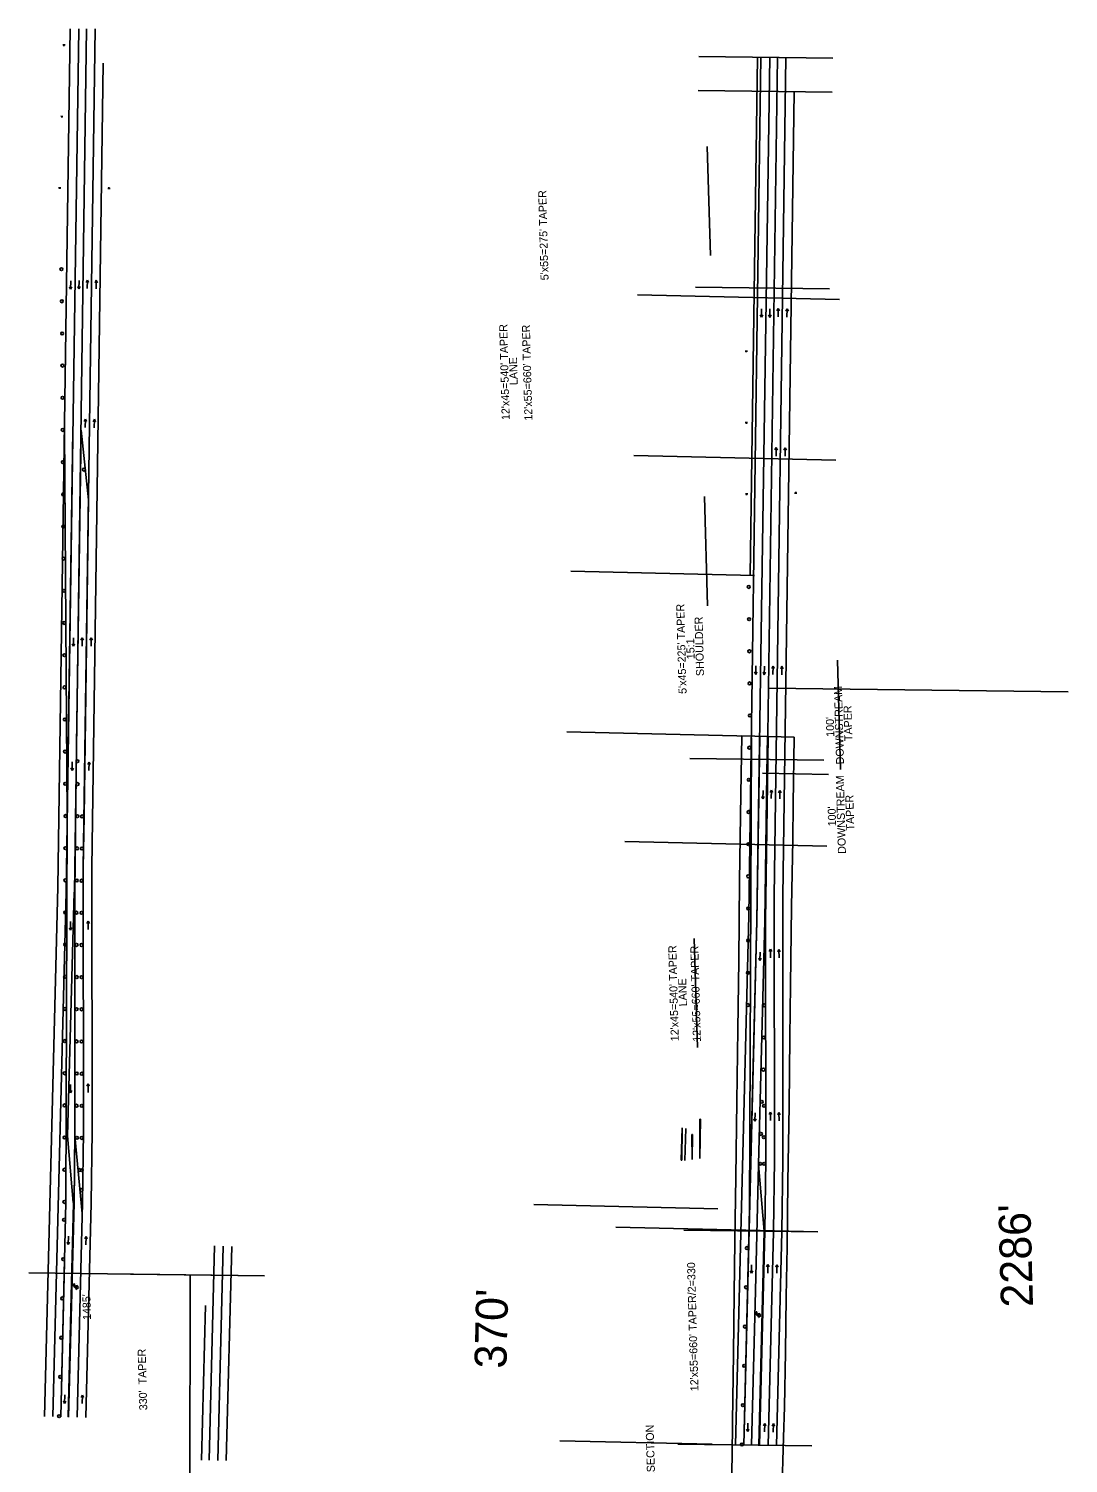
# Model space of a CAD drawing. Extents: x 1651568 to 1653044, y 601329 to 611807.
# Drawn here: x 1651589 to 1653044, y 609799 to 611807 of the extents above; entities that cross this region are included whole.
import ezdxf

# ---------------------------------------------------------------- set-up
doc = ezdxf.new("R2010")
doc.units = 0
for name, color, linetype in [('CM_Corridor_Design', 7, 'Continuous'), ('Default', 7, 'Continuous'), ('DR_X_Storm_Sewer', 7, 'Continuous'), ('DT_X_Break_Line', 7, 'Continuous'), ('GE_P_Alignment_500_Cardinal_Points', 7, 'Continuous'), ('GE_P_Alignment_500_Distances', 7, 'Continuous'), ('PF_P_Grade_Line', 7, 'Continuous'), ('PF_X_Ground_Line', 7, 'Continuous'), ('PF_X_Ground_Line_LT', 7, 'Continuous'), ('PF_X_Ground_Line_RT', 7, 'Continuous'), ('PV_P_EOP', 7, 'Continuous'), ('RW_X_Esmt_LA', 7, 'Continuous'), ('SC_Scratch3', 7, 'Continuous'), ('UT_X_Gas', 7, 'Continuous'), ('UT_X_Sanitary_Line', 7, 'Continuous')]:
    doc.layers.add(name, color=color, linetype=linetype)

msp = doc.modelspace()

# ---------------------------------------------------------------- linework, layer by layer
at = {"layer": 'CM_Corridor_Design'}
for p, q in [((1651647.5, 611442), (1651647.8, 611453.9)), ((1651659.1, 611442.5), (1651659.4, 611454.4)), ((1651671, 611454.9), (1651669.2, 611451.5)), ((1651671, 611454.9), (1651670.7, 611443)), ((1651671, 611454.9), (1651672.6, 611451.5)), ((1651683.5, 611454.6), (1651681.7, 611451.2)), ((1651683.5, 611454.6), (1651683.3, 611442.7)), ((1651683.5, 611454.6), (1651685.2, 611451.2)), ((1651647.5, 611442), (1651645.9, 611445.5)), ((1651647.5, 611442), (1651649.3, 611445.4)), ((1651659.1, 611442.5), (1651657.5, 611445.9)), ((1651659.1, 611442.5), (1651660.9, 611445.9)), ((1652614.7, 611402.9), (1652614.9, 611414.7)), ((1652626.3, 611402.7), (1652626.5, 611414.6)), ((1652638.1, 611415.1), (1652636.3, 611411.7)), ((1652638.1, 611415.1), (1652637.9, 611403.2)), ((1652638.1, 611415.1), (1652639.8, 611411.7)), ((1652650.7, 611414.8), (1652648.9, 611411.4)), ((1652650.7, 611414.8), (1652650.4, 611402.9)), ((1652650.7, 611414.8), (1652652.3, 611411.4)), ((1652614.7, 611402.9), (1652613, 611406.3)), ((1652614.7, 611402.9), (1652616.4, 611406.2)), ((1652626.3, 611402.7), (1652624.6, 611406.1)), ((1652626.3, 611402.7), (1652628.1, 611406)), ((1651668.3, 611260.3), (1651666.5, 611256.9)), ((1651668.3, 611260.3), (1651668, 611248.4)), ((1651668.3, 611260.3), (1651669.9, 611256.8)), ((1651680.8, 611260), (1651679, 611256.6)), ((1651680.8, 611260), (1651680.6, 611248.1)), ((1651680.8, 611260), (1651682.5, 611256.6)), ((1652635.4, 611220.4), (1652633.6, 611217.1)), ((1652635.4, 611220.4), (1652635.2, 611208.6)), ((1652635.4, 611220.4), (1652637.1, 611217)), ((1652648, 611220.2), (1652646.2, 611216.8)), ((1652648, 611220.2), (1652647.7, 611208.3)), ((1652648, 611220.2), (1652649.6, 611216.7)), ((1651651.4, 610942.5), (1651651.6, 610954.3)), ((1651663.7, 610954.4), (1651661.9, 610951.1)), ((1651663.7, 610954.4), (1651663.5, 610942.6)), ((1651663.7, 610954.4), (1651665.4, 610951)), ((1651676.3, 610954.1), (1651674.5, 610950.8)), ((1651676.3, 610954.1), (1651676.1, 610942.3)), ((1651676.3, 610954.1), (1651678, 610950.7)), ((1651651.4, 610942.5), (1651649.7, 610945.9)), ((1651651.4, 610942.5), (1651653.2, 610945.8)), ((1652606.6, 610903), (1652606.8, 610914.9)), ((1652618.5, 610902.6), (1652618.8, 610914.5)), ((1652630.9, 610914.6), (1652629.1, 610911.3)), ((1652630.9, 610914.6), (1652630.7, 610902.8)), ((1652630.9, 610914.6), (1652632.5, 610911.2)), ((1652643.4, 610914.3), (1652641.7, 610911)), ((1652643.4, 610914.3), (1652643.2, 610902.5)), ((1652643.4, 610914.3), (1652645.1, 610910.9)), ((1652606.6, 610903), (1652604.9, 610906.4)), ((1652606.6, 610903), (1652608.3, 610906.4)), ((1652618.5, 610902.6), (1652616.9, 610906.1)), ((1652618.5, 610902.6), (1652620.3, 610906)), ((1651649.6, 610768.7), (1651648, 610772.1)), ((1651649.6, 610768.7), (1651649.9, 610780.5)), ((1651649.6, 610768.7), (1651651.4, 610772)), ((1651673.3, 610780.4), (1651671.5, 610777.1)), ((1651673.3, 610780.4), (1651673.1, 610768.6)), ((1651673.3, 610780.4), (1651675, 610777)), ((1652616.8, 610728.9), (1652615.1, 610732.3)), ((1652616.8, 610728.9), (1652617, 610740.7)), ((1652616.8, 610728.9), (1652618.6, 610732.2)), ((1652628.5, 610741), (1652626.7, 610737.6)), ((1652628.5, 610741), (1652628.3, 610729.1)), ((1652628.5, 610741), (1652630.1, 610737.6)), ((1652640.5, 610740.6), (1652638.7, 610737.3)), ((1652640.5, 610740.6), (1652640.2, 610728.7)), ((1652640.5, 610740.6), (1652642.1, 610737.2)), ((1651647.6, 610545.2), (1651645.9, 610548.5)), ((1651647.6, 610545.2), (1651647.4, 610557.1)), ((1651647.6, 610545.2), (1651649.3, 610548.6)), ((1651672.1, 610557.8), (1651670.4, 610554.4)), ((1651672.1, 610557.8), (1651672.3, 610545.9)), ((1651672.1, 610557.8), (1651673.9, 610554.5)), ((1652612.5, 610502.5), (1652612.9, 610514.3)), ((1652627.2, 610518.4), (1652625.6, 610515)), ((1652627.2, 610518.4), (1652627.4, 610506.5)), ((1652627.2, 610518.4), (1652629, 610515)), ((1652639.2, 610518), (1652637.6, 610514.6)), ((1652639.2, 610518), (1652639.4, 610506.1)), ((1652639.2, 610518), (1652641, 610514.6)), ((1652612.5, 610502.5), (1652610.9, 610505.9)), ((1652612.5, 610502.5), (1652614.4, 610505.8)), ((1651647.5, 610317.3), (1651647.3, 610329.1)), ((1651671.9, 610329.9), (1651670.3, 610326.5)), ((1651671.9, 610329.9), (1651672.1, 610318)), ((1651671.9, 610329.9), (1651673.7, 610326.5)), ((1651647.5, 610317.3), (1651645.7, 610320.6)), ((1651647.5, 610317.3), (1651649.2, 610320.7)), ((1652605.5, 610277.7), (1652605.7, 610289.6)), ((1652627.1, 610290.4), (1652625.4, 610287)), ((1652627.1, 610290.4), (1652627.3, 610278.6)), ((1652627.1, 610290.4), (1652628.9, 610287.1)), ((1652639.1, 610290.1), (1652637.4, 610286.6)), ((1652639.1, 610290.1), (1652639.3, 610278.2)), ((1652639.1, 610290.1), (1652640.9, 610286.7)), ((1652605.5, 610277.7), (1652603.8, 610281.1)), ((1652605.5, 610277.7), (1652607.3, 610281.1)), ((1651644.3, 610105), (1651642.7, 610108.5)), ((1651644.3, 610105), (1651644.6, 610116.9)), ((1651644.3, 610105), (1651646.1, 610108.4)), ((1651669.3, 610116.5), (1651667.5, 610113.2)), ((1651669.3, 610116.5), (1651668.9, 610104.6)), ((1651669.3, 610116.5), (1651670.9, 610113.1)), ((1652600.5, 610064.9), (1652598.9, 610068.4)), ((1652600.5, 610064.9), (1652600.9, 610076.8)), ((1652600.5, 610064.9), (1652602.4, 610068.3)), ((1652623.7, 610077.1), (1652621.9, 610073.8)), ((1652623.7, 610077.1), (1652623.4, 610065.2)), ((1652623.7, 610077.1), (1652625.4, 610073.7)), ((1652636.4, 610076.7), (1652634.6, 610073.4)), ((1652636.4, 610076.7), (1652636.1, 610064.8)), ((1652636.4, 610076.7), (1652638.1, 610073.3)), ((1651639.1, 609882.8), (1651637.5, 609886.2)), ((1651639.1, 609882.8), (1651639.5, 609894.6)), ((1651639.1, 609882.8), (1651641, 609886.1)), ((1651664.1, 609894.2), (1651662.3, 609890.9)), ((1651664.1, 609894.2), (1651663.8, 609882.4)), ((1651664.1, 609894.2), (1651665.8, 609890.8)), ((1652595.4, 609843.3), (1652593.7, 609846.7)), ((1652595.4, 609843.3), (1652595.7, 609855.1)), ((1652595.4, 609843.3), (1652597.2, 609846.6)), ((1652619.3, 609854.8), (1652617.5, 609851.5)), ((1652619.3, 609854.8), (1652618.9, 609842.9)), ((1652619.3, 609854.8), (1652620.9, 609851.4)), ((1652631.3, 609854.4), (1652629.5, 609851.1)), ((1652631.3, 609854.4), (1652630.9, 609842.6)), ((1652631.3, 609854.4), (1652632.9, 609851))]:
    msp.add_line(p, q, dxfattribs=at)
at = {"layer": 'Default'}
for p, q in [((1652714.7, 611765.6), (1652527, 611768)), ((1652587, 610817), (1652660.3, 610815.3)), ((1652642.7, 609739.1), (1652645.7, 609834.8)), ((1652572.1, 609742), (1652573.5, 609808.2))]:
    msp.add_line(p, q, dxfattribs=at)
for points in [[(1652573.5, 609808.2), (1652574.2, 609856.9), (1652575.3, 609952.6), (1652576.5, 610036.1), (1652577.5, 610110), (1652578.8, 610199.8), (1652580.1, 610305.2), (1652581.5, 610406), (1652583, 610502.8), (1652584, 610614.2), (1652585.9, 610735.6), (1652587, 610817)], [(1652660.3, 610815.3), (1652659, 610721.7), (1652658.4, 610671.7), (1652656.9, 610577.9), (1652655.5, 610468.3), (1652654.6, 610395.3), (1652653.3, 610299), (1652651.7, 610192.7), (1652650.5, 610101.9), (1652649.4, 610032), (1652648.2, 609954.3), (1652646.7, 609877.8), (1652645.7, 609834.8)]]:
    msp.add_lwpolyline(points, dxfattribs=at)
at = {"layer": 'DR_X_Storm_Sewer'}
msp.add_line((1651642.8, 610704.8), (1651650.8, 611244.8), dxfattribs=at)
msp.add_lwpolyline([(1652598, 610154.4), (1652608.4, 610558.3), (1652612.2, 610816.3)], dxfattribs=at)
at = {"layer": 'DT_X_Break_Line'}
for centre in [(1651634.7, 611470.2), (1651635.3, 611425.2), (1651635.7, 611380.1), (1651636.1, 611335.1), (1651636.4, 611290.1), (1651636.5, 611245.1), (1651636.9, 611200.1), (1651666.2, 611189.6), (1651637.2, 611155), (1651637.5, 611110), (1651637.8, 611065), (1651638.2, 611020), (1652596.8, 611025.4), (1651638.5, 610975), (1652597.3, 610980.4), (1651638.8, 610929.9), (1652597.7, 610935.4), (1652598.1, 610890.4), (1651639.1, 610884.9), (1651639.5, 610839.9), (1652598.5, 610845.4), (1651639.8, 610794.9), (1652597.7, 610800.4), (1651657.1, 610781.6), (1651640.1, 610749.9), (1651657.4, 610749.5), (1652596.9, 610755.4), (1652596.6, 610710.4), (1651640.5, 610704.8), (1651657, 610704.5), (1651663.6, 610704.3), (1651640.3, 610659.8), (1651656.6, 610659.5), (1651663.4, 610659.3), (1652596.4, 610665.4), (1651640.2, 610614.8), (1651656.2, 610614.5), (1651662.7, 610614.3), (1652596.2, 610620.4), (1651640, 610569.8), (1651655.7, 610569.5), (1651662.9, 610569.3), (1652596.1, 610575.4), (1652596, 610530.4), (1651639.9, 610524.8), (1651656, 610524.4), (1651662.7, 610524.3), (1651639.8, 610479.8), (1651656.1, 610479.4), (1651662.9, 610479.3), (1652595.8, 610485.4), (1651639.6, 610434.8), (1651655.9, 610434.4), (1651662.9, 610434.3), (1652595.7, 610440.3), (1652618.4, 610439.8), (1651639.5, 610389.8), (1651655.9, 610389.4), (1651662.9, 610389.2), (1652617.8, 610394.8), (1652617.3, 610349.8), (1651639.3, 610344.8), (1651656.1, 610344.4), (1651663.1, 610344.2), (1651639.2, 610299.8), (1651656, 610299.4), (1651663.1, 610299.2), (1652615, 610304.8), (1652618.3, 610299.2), (1651639, 610254.8), (1651656.4, 610254.4), (1651663.1, 610254.2), (1652613.9, 610259.9), (1652618.1, 610255.3), (1651638.9, 610209.8), (1651660.2, 610209.3), (1651663.3, 610209.2), (1652612.8, 610218.1), (1652618.3, 610218), (1651662.6, 610181.3), (1651638.8, 610164.7), (1651638.4, 610139.7), (1651637.2, 610084.7), (1652594.3, 610100.2), (1652593.1, 610045.2), (1651635.7, 610029.7), (1652591.6, 609990.2), (1651634.4, 609974.7), (1652590.4, 609935.3), (1651632.9, 609919.8), (1651631.4, 609864.8), (1652588.8, 609880.3), (1652587.3, 609825.3)]:
    msp.add_circle(centre, 2, dxfattribs=at)
at = {"layer": 'GE_P_Alignment_500_Cardinal_Points'}
for p, q in [((1652598.8, 611041.8), (1652608.9, 611766.9)), ((1652605.1, 611041.6), (1652347.6, 611047.6)), ((1652599.9, 610816.7), (1652342.4, 610822.7)), ((1652502.2, 610223.2), (1652503.8, 610268.2)), ((1652503.2, 610223.2), (1652503.8, 610268.2)), ((1652507.3, 610222.7), (1652509, 610267.6)), ((1652529.4, 610280.5), (1652528.4, 610280.5)), ((1652528.6, 610225.5), (1652528.4, 610280.5)), ((1652528.6, 610225.5), (1652529.4, 610280.5)), ((1652518.3, 610259.1), (1652517.3, 610259.1)), ((1652517.3, 610259.1), (1652517.7, 610224.1)), ((1652517.7, 610224.1), (1652518.3, 610259.1)), ((1652503.2, 610223.2), (1652502.2, 610223.2)), ((1652553.4, 610155.1), (1652295.9, 610161.1)), ((1652545.8, 609825.5), (1652332.4, 609830.5))]:
    msp.add_line(p, q, dxfattribs=at)
at = {"layer": 'GE_P_Alignment_500_Distances'}
for p, q in [((1652713.6, 611717.8), (1652525.9, 611720.1)), ((1652543.2, 611489.1), (1652538.7, 611642)), ((1652723.8, 611427.6), (1652441, 611434.1)), ((1652710.1, 611442.8), (1652522.5, 611445.1)), ((1652718.6, 611202.6), (1652435.8, 611209.2)), ((1652539.3, 610999.1), (1652534.8, 611152)), ((1652725.4, 610770.1), (1652720.9, 610923)), ((1653044.2, 610878.6), (1652624.6, 610883.8)), ((1652701.9, 610782.8), (1652514.2, 610785.2)), ((1652708.4, 610762.7), (1652615.9, 610764.9)), ((1652706.1, 610662.8), (1652423.3, 610669.3)), ((1652525, 610380.7), (1652520.4, 610533.6)), ((1652693.6, 610122.9), (1652410.8, 610129.5)), ((1652693.6, 610122.9), (1652505.9, 610125.3)), ((1651918.9, 610061.5), (1651588.9, 610065.6)), ((1651918.9, 610061.5), (1651731.2, 610063.8)), ((1652685, 609823.2), (1652497.4, 609825.5))]:
    msp.add_line(p, q, dxfattribs=at)
at = {"layer": 'PF_P_Grade_Line'}
for p, q in [((1651629.9, 610605.1), (1651646.8, 611806.7)), ((1651677.3, 610632.2), (1651693.1, 611758.3)), ((1652597.1, 610565.3), (1652613.9, 611766.9)), ((1652644.5, 610592.4), (1652660.3, 611718.4)), ((1651677.3, 610632.2), (1651677.5, 610263.4)), ((1651611.2, 609864.6), (1651629.9, 610605.1)), ((1652644.5, 610592.4), (1652644.7, 610223.6)), ((1652578.4, 609824.8), (1652597.1, 610565.3)), ((1651676.3, 610163.3), (1651677.5, 610263.1)), ((1652643.4, 610123.5), (1652644.7, 610223.3)), ((1651668.7, 609863.1), (1651676.3, 610163)), ((1652635.9, 609823.3), (1652643.4, 610123.2)), ((1651865.5, 609802.6), (1651873.1, 610102.5)), ((1651633.7, 609864), (1651639.2, 610080.3)), ((1652600.9, 609824.2), (1652606.3, 610040.5)), ((1651831, 609803.5), (1651836.5, 610019.7))]:
    msp.add_line(p, q, dxfattribs=at)
at = {"layer": 'PF_X_Ground_Line'}
for p, q in [((1651639.8, 611784), (1651636.6, 611784)), ((1651638.2, 611784), (1651638.2, 611782.4)), ((1651638.2, 611784), (1651638.2, 611784)), ((1651636.9, 611684), (1651633.7, 611684.1)), ((1651635.3, 611684), (1651635.3, 611682.4)), ((1651635.3, 611684), (1651635.3, 611684)), ((1651634, 611584), (1651630.8, 611584.1)), ((1651632.4, 611584.1), (1651632.3, 611582.5)), ((1651632.4, 611584.1), (1651632.4, 611584.1)), ((1651699.5, 611583.2), (1651702.7, 611583.2)), ((1651701.1, 611583.2), (1651701.1, 611584.8)), ((1651701.1, 611583.2), (1651701.1, 611583.2)), ((1652594.9, 611355.5), (1652591.7, 611355.5)), ((1652593.3, 611355.5), (1652593.3, 611353.9)), ((1652593.3, 611355.5), (1652593.3, 611355.5)), ((1652595.2, 611255.5), (1652592, 611255.5)), ((1652593.6, 611255.5), (1652593.6, 611253.9)), ((1652593.6, 611255.5), (1652593.6, 611255.5)), ((1652595.5, 611155.5), (1652592.3, 611155.5)), ((1652593.9, 611155.5), (1652593.9, 611153.9)), ((1652593.9, 611155.5), (1652593.9, 611155.5)), ((1652661, 611156.8), (1652664.2, 611156.8)), ((1652662.6, 611156.8), (1652662.6, 611158.4)), ((1652662.6, 611156.8), (1652662.6, 611156.8))]:
    msp.add_line(p, q, dxfattribs=at)
at = {"layer": 'PF_X_Ground_Line_LT'}
for p, q in [((1651652.8, 610598), (1651669.8, 611806.4)), ((1652620, 610558.2), (1652636.9, 611766.6)), ((1651643.3, 610257.1), (1651652.3, 610598)), ((1651653.3, 610598), (1651653.5, 610263.4)), ((1652610.5, 610217.3), (1652619.5, 610558.2)), ((1652620.5, 610558.2), (1652620.7, 610223.6)), ((1651651.3, 610163.7), (1651643.3, 610257.1)), ((1651652.3, 610163.6), (1651653.5, 610263.4)), ((1652618.4, 610123.8), (1652610.5, 610217.3)), ((1652619.4, 610123.8), (1652620.7, 610223.6)), ((1651644.2, 609863.8), (1651651.8, 610163.6)), ((1652611.4, 609824), (1652618.9, 610123.8)), ((1651841.5, 609803.2), (1651849.1, 610103.1))]:
    msp.add_line(p, q, dxfattribs=at)
at = {"layer": 'PF_X_Ground_Line_RT'}
msp.add_line((1651853.5, 609802.9), (1651861.1, 610102.8), dxfattribs=at)
for points in [[(1651622.7, 609864.3), (1651641.3, 610598.1), (1651659.2, 611806.5)], [(1651656.7, 609863.4), (1651664.3, 610163.3), (1651664.3, 610163.5), (1651665.5, 610263.2), (1651665.5, 610263.4), (1651665.3, 610632.3), (1651681.8, 611806.3)], [(1652589.9, 609824.5), (1652608.4, 610558.3), (1652626.3, 611766.7)], [(1652623.9, 609823.6), (1652631.4, 610123.5), (1652631.4, 610123.7), (1652632.7, 610223.4), (1652632.7, 610223.6), (1652632.5, 610592.5), (1652648.9, 611766.4)]]:
    msp.add_lwpolyline(points, dxfattribs=at)
at = {"layer": 'PV_P_EOP'}
for p, q in [((1651638.9, 611245), (1651642.8, 610704.8)), ((1652598, 610154.4), (1652600.6, 610814.2)), ((1651642.8, 610704.8), (1651641.1, 610163.8)), ((1651641.1, 610163.8), (1651633.7, 609864)), ((1652598, 610154.4), (1652589.9, 609824.5)), ((1651649.6, 610055.4), (1651644.7, 609863.7)), ((1651815.1, 610062.8), (1651813.5, 609072.7))]:
    msp.add_line(p, q, dxfattribs=at)
at = {"layer": 'RW_X_Esmt_LA'}
for p, q in [((1651662.4, 611244.7), (1651655.9, 610804.5)), ((1651672.5, 611147.5), (1651662.4, 611244.7)), ((1651666.3, 610704.3), (1651672.5, 611147.5)), ((1652623.1, 610816.4), (1652622.4, 610764.7)), ((1652622.7, 610717.1), (1652624.1, 610816.4)), ((1651655.9, 610804.5), (1651653.3, 610598)), ((1652622.4, 610764.7), (1652619.5, 610558.2)), ((1652620.5, 610558.2), (1652622.7, 610717.1)), ((1651665.3, 610632.3), (1651666.3, 610704.3)), ((1651665.5, 610263.2), (1651665.3, 610632.3)), ((1651653.3, 610598), (1651653.5, 610263.4)), ((1652619.5, 610558.2), (1652610.5, 610217.3)), ((1652620.7, 610223.6), (1652620.5, 610558.2)), ((1651653.5, 610263.4), (1651653.4, 610257)), ((1651653.4, 610257), (1651663.9, 610148.5)), ((1651664.3, 610163.5), (1651665.5, 610263.2)), ((1652610.5, 610217.3), (1652618.4, 610123.8)), ((1652619.4, 610124), (1652620.7, 610223.5)), ((1651656.7, 609863.4), (1651664.3, 610163.5)), ((1652610.9, 609823.8), (1652618.4, 610123.8)), ((1652611.9, 609823.9), (1652619.4, 610124))]:
    msp.add_line(p, q, dxfattribs=at)
for centre, start, end in [((1651666.1, 610632.3), 179.1959, 180.0299), ((1652621.3, 610558.2), 179.1959, 180.0301), ((1651664.7, 610263.2), 359.3037, 0.0299), ((1652619.8, 610223.6), 359.3043, 0.0301)]:
    msp.add_arc(centre, 0.833, start, end, dxfattribs=at)
at = {"layer": 'UT_X_Gas'}
for p, q in [((1651652.3, 610163.6), (1651653.4, 610257)), ((1652606.3, 610040.5), (1652610.5, 610217.3)), ((1651649.6, 610055.4), (1651652.3, 610163.6))]:
    msp.add_line(p, q, dxfattribs=at)
at = {"layer": 'UT_X_Sanitary_Line'}
for p, q in [((1651652.2, 610050.1), (1651652.1, 610047.6)), ((1651653.2, 610050.1), (1651652.2, 610050.1)), ((1651653.1, 610048.2), (1651653.2, 610050.1)), ((1651655.5, 610050), (1651655.5, 610050)), ((1651658.4, 610045), (1651655.8, 610048.1)), ((1651655.8, 610048.1), (1651656.1, 610045.9)), ((1651655.3, 610042), (1651658.4, 610045)), ((1651656, 610044.3), (1651655.3, 610042)), ((1651655.3, 610042), (1651655.3, 610042)), ((1651656.1, 610045.9), (1651655.4, 610045.9)), ((1651655.4, 610044.3), (1651656, 610044.3)), ((1652607.4, 610011), (1652607.3, 610008.5)), ((1652608.4, 610011), (1652607.4, 610011)), ((1652608.4, 610009.1), (1652608.4, 610011)), ((1652611.3, 610006.7), (1652610.6, 610006.7)), ((1652610.7, 610010.9), (1652610.7, 610010.9)), ((1652613.6, 610005.9), (1652611, 610009)), ((1652611, 610009), (1652611.3, 610006.7)), ((1652610.6, 610002.9), (1652613.6, 610005.9)), ((1652610.6, 610005.1), (1652611.3, 610005.1)), ((1652611.3, 610005.1), (1652610.6, 610002.9)), ((1652610.6, 610002.9), (1652610.6, 610002.9))]:
    msp.add_line(p, q, dxfattribs=at)
for centre, radius, end in [((1651655.4, 610047.6), 3.28, 269.5805), ((1651655.4, 610048.2), 2.3, 268.672), ((1652610.6, 610008.4), 3.28, 269.5805), ((1652610.7, 610009), 2.3, 268.672)]:
    msp.add_arc(centre, radius, 178.672, end, dxfattribs=at)

# ---------------------------------------------------------------- texts
at = {"layer": 'GE_P_Alignment_500_Cardinal_Points'}
for s, height, p in [("5'x55=275' TAPER", 11.2, (1652316.7, 611454.8)), ("12'x45=540' TAPER", 11.2, (1652262.3, 611259.1)), ("12'x55=660' TAPER", 11.2, (1652294.1, 611258.3)), ('LANE', 11.2, (1652273.5, 611308)), ("5'x45=225' TAPER", 11.2, (1652509.9, 610875.9)), ('SHOULDER', 11.2, (1652534.4, 610900.8)), ('15:1', 11.2, (1652521.2, 610924.4)), ('DOWNSTREAM', 11.2, (1652730.3, 610777.2)), ('TAPER', 11.2, (1652742, 610809.8)), ("100'", 11.2, (1652716.7, 610815.8)), ('DOWNSTREAM', 11.2, (1652732.9, 610652)), ('TAPER', 11.2, (1652744.6, 610684.6)), ("100'", 11.2, (1652719.2, 610690.5)), ("12'x45=540' TAPER", 11.2, (1652499, 610389.7)), ("12'x55=660' TAPER", 11.2, (1652529.9, 610389)), ('LANE', 11.2, (1652510.3, 610438.6)), ("2286'", 44.8, (1652994.9, 610017.8)), ("12'x55=660' TAPER/2=330", 11.2, (1652526.5, 609899.9)), ("1485'", 11.2, (1651676.1, 609999.6)), ("330'  TAPER", 11.2, (1651754.9, 609873.3)), ('INTERSECTION', 11.2, (1652466.7, 609741.6))]:
    msp.add_text(s, height=height, rotation=91.5443, dxfattribs=at).set_placement(p)
at = {"layer": 'SC_Scratch3'}
msp.add_text("370'", height=44.8, rotation=88.672, dxfattribs=at).set_placement((1652257.6, 609931.1))

doc.saveas('drawing.dxf')
